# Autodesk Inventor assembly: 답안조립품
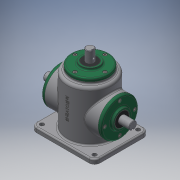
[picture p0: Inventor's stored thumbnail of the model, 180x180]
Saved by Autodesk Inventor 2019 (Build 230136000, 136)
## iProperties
Created: 2020-12
Part Number: 답안조립품
Material: 일반
Document SubType Name: Assembly
Designer: jun-1-10
Author: jun-1-10
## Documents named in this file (16)
- C:\Users\jun-1-10\Desktop\701207V1006\답안조립품.iam
- C:\Users\jun-1-10\Desktop\701207V1006\본체.ipt
- C:\Users\jun-1-10\Desktop\701207V1006\메인 베벨기어.ipt
- C:\Users\jun-1-10\Desktop\701207V1006\메인 축.ipt
- 메인 축.ipt
- C:\Users\jun-1-10\Desktop\701207V1006\베어링 6203.ipt
- C:\Users\jun-1-10\Desktop\701207V1006\볼트 M4.ipt
- 볼트 M4.ipt
- C:\Users\jun-1-10\Desktop\701207V1006\서브 베벨기어.ipt
- C:\Users\jun-1-10\Desktop\701207V1006\서브 축.ipt
- 서브 축.ipt
- C:\Users\jun-1-10\Desktop\701207V1006\오일 실.ipt
- 오일 실.ipt
- C:\Users\jun-1-10\Desktop\701207V1006\커버.ipt
- C:\Users\jun-1-10\Desktop\701207V1006\키 4x4.ipt
- C:\Users\jun-1-10\Desktop\701207V1006\키 5x5.ipt
